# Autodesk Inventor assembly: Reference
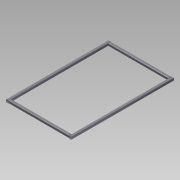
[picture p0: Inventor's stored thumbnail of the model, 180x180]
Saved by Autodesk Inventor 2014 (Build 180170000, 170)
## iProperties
Company: NHTSA/VRTC
Created: 2013-10
Part Number: Reference
Document SubType Name: Assembly
Designer: Dave Walker
Project: CHILD SIDE IMPACT SLED
Description: SUBFRAME ASSEMBLY
Author: Dave Walker
Title: Subframe Assembly
Subject: Child Side Impact Sled
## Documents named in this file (3)
- B:\VRTC_DWG\BIO\Non-P572\Child Side-Frontal Impact Sled\Side Impact Sled\Sub-Frame\Subframe Assembly.iam
- B:\VRTC_DWG\BIO\Non-P572\Child Side-Frontal Impact Sled\Side Impact Sled\Sub-Frame\Subframe Side Tube.ipt
- B:\VRTC_DWG\BIO\Non-P572\Child Side-Frontal Impact Sled\Side Impact Sled\Sub-Frame\Subframe End Tube.ipt
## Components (4 placed, 2 different names)
1. Subframe Side Tube:1 — Mate:1, Flush:1, Mate:3, Flush:3
2. Subframe Side Tube:2 — Mate:2, Flush:1, Flush:2, Mate:4, Flush:4, Flush:5, Mate:5, Flush:6, Flush:7
3. Subframe End Tube:1 — Mate:4, Flush:4, Flush:5
4. Subframe End Tube:2 — Mate:5, Flush:6, Flush:7
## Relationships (12: Flush 7, Mate 5)
- Mate:1: Subframe Side Tube:1
- Mate:2: Subframe Side Tube:2
- Flush:1: Subframe Side Tube:1 ↔ Subframe Side Tube:2
- Flush:2: Subframe Side Tube:2
- Mate:3: Subframe Side Tube:1
- Flush:3: Subframe Side Tube:1
- Mate:4: Subframe Side Tube:2 ↔ Subframe End Tube:1
- Flush:4: Subframe Side Tube:2 ↔ Subframe End Tube:1
- Flush:5: Subframe Side Tube:2 ↔ Subframe End Tube:1
- Mate:5: Subframe Side Tube:2 ↔ Subframe End Tube:2
- Flush:6: Subframe Side Tube:2 ↔ Subframe End Tube:2
- Flush:7: Subframe Side Tube:2 ↔ Subframe End Tube:2
